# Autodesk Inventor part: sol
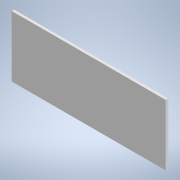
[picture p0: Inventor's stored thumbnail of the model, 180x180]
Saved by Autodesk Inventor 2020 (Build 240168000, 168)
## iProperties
Created: 2023-10
Part Number: sol
Material: Générique
Document SubType Name: Modeling
Designer: bruno
Density: 1 g/cm^3
Appearance: Pin jaune - Massif moiré clair faible lustre
Author: bruno
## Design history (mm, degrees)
node "Plan de construction1"
node "Plan de construction2"
sketch "Esquisse2"
  geometry: L1 (-41.102, 208.081)-(574.192, 208.081); L2 (574.192, 208.081)-(574.192, -35.836); L3 (574.192, -35.836)-(-41.102, -35.836); L4 (-41.102, -35.836)-(-41.102, 208.081); 1 further point
  constraints: 8 end point, 2 parallel, 1 horizontal, 1 perpendicular
extrude "Extrusion1" new body sketch "Esquisse2" distance "d0" = 10; taper "d1" = 0 deg
node "Solide1"
